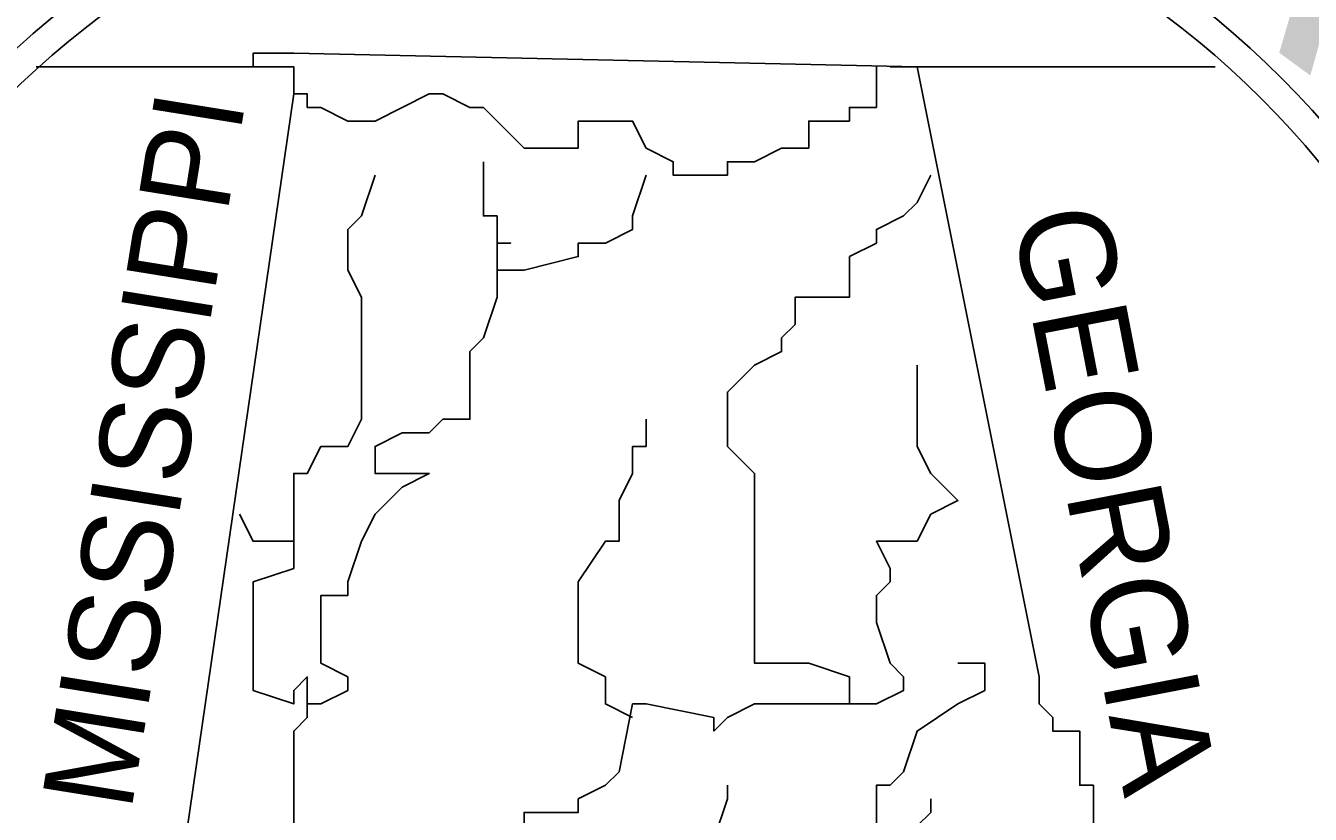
# Model space of a CAD drawing. Extents: x 0 to 1700, y 31 to 1131.
# Drawn here: x 915.89 to 940.79, y 79.02 to 94.3 of the extents above; entities that cross this region are included whole.
import ezdxf

# ---------------------------------------------------------------- set-up
doc = ezdxf.new("R2010")
doc.units = 0
doc.layers.add('great seal', color=7, linetype='Continuous')

msp = doc.modelspace()

# ---------------------------------------------------------------- linework, layer by layer
at = {"layer": 'great seal'}
for p, q in [((921.082, 93.503), (916.09, 93.503)), ((921.082, 93.503), (916.09, 93.503)), ((921.082, 93.503), (916.09, 93.503)), ((932.644, 93.503), (938.95, 93.503)), ((932.644, 93.503), (938.95, 93.503)), ((932.644, 93.503), (938.95, 93.503)), ((927.651, 80.891), (927.651, 80.891)), ((927.651, 80.891), (927.651, 80.891)), ((927.651, 80.891), (927.651, 80.891)), ((927.651, 80.891), (927.651, 80.891)), ((927.651, 80.891), (927.651, 80.891)), ((927.651, 80.891), (927.651, 80.891))]:
    msp.add_line(p, q, dxfattribs=at)
for points in [[(918.717, 76.687), (921.082, 92.978), (921.082, 93.503), (921.082, 93.503), (921.082, 93.503), (920.294, 93.503), (920.294, 93.766), (921.082, 93.766), (933.169, 93.503), (935.534, 81.679), (935.534, 81.154), (935.797, 80.891), (935.797, 80.628), (935.797, 80.628), (936.323, 80.628), (936.323, 79.84), (936.323, 79.577), (936.585, 79.577), (936.585, 79.314), (936.585, 79.314), (936.585, 79.051), (936.585, 78.789)], [(918.717, 76.687), (921.082, 92.978), (921.082, 93.503), (921.082, 93.503), (921.082, 93.503), (920.294, 93.503), (920.294, 93.766), (921.082, 93.766), (933.169, 93.503), (935.534, 81.679), (935.534, 81.154), (935.797, 80.891), (935.797, 80.628), (935.797, 80.628), (936.323, 80.628), (936.323, 79.84), (936.323, 79.577), (936.585, 79.577), (936.585, 79.314), (936.585, 79.314), (936.585, 79.051), (936.585, 78.789)], [(918.717, 76.687), (921.082, 92.978), (921.082, 93.503), (921.082, 93.503), (921.082, 93.503), (920.294, 93.503), (920.294, 93.766), (921.082, 93.766), (933.169, 93.503), (935.534, 81.679), (935.534, 81.154), (935.797, 80.891), (935.797, 80.628), (935.797, 80.628), (936.323, 80.628), (936.323, 79.84), (936.323, 79.577), (936.585, 79.577), (936.585, 79.314), (936.585, 79.314), (936.585, 79.051), (936.585, 78.789)], [(932.381, 93.503), (932.381, 93.503), (932.381, 93.503), (932.381, 92.978), (932.381, 92.715), (932.381, 92.715), (931.856, 92.715), (931.856, 92.715), (931.856, 92.452), (931.067, 92.452), (931.067, 91.927), (930.542, 91.927), (930.016, 91.664), (929.753, 91.664), (929.491, 91.664), (929.491, 91.401), (929.228, 91.401), (929.228, 91.401), (928.44, 91.401), (928.44, 91.401), (928.44, 91.664), (927.914, 91.927), (927.651, 92.452), (927.651, 92.452), (927.126, 92.452), (926.6, 92.452), (926.6, 91.927), (925.549, 91.927), (925.024, 92.452), (924.761, 92.715), (924.498, 92.715), (923.973, 92.978), (923.71, 92.978), (923.184, 92.715), (923.184, 92.715), (922.659, 92.452), (922.396, 92.452), (922.133, 92.452), (921.608, 92.715), (921.608, 92.715), (921.608, 92.715), (921.345, 92.715), (921.345, 92.715), (921.345, 92.715), (921.345, 92.978), (921.082, 92.978), (921.082, 93.503), (921.082, 93.503), (921.082, 93.503)], [(932.381, 93.503), (932.381, 93.503), (932.381, 93.503), (932.381, 92.978), (932.381, 92.715), (932.381, 92.715), (931.856, 92.715), (931.856, 92.715), (931.856, 92.452), (931.067, 92.452), (931.067, 91.927), (930.542, 91.927), (930.016, 91.664), (929.753, 91.664), (929.491, 91.664), (929.491, 91.401), (929.228, 91.401), (929.228, 91.401), (928.44, 91.401), (928.44, 91.401), (928.44, 91.664), (927.914, 91.927), (927.651, 92.452), (927.651, 92.452), (927.126, 92.452), (926.6, 92.452), (926.6, 91.927), (925.549, 91.927), (925.024, 92.452), (924.761, 92.715), (924.498, 92.715), (923.973, 92.978), (923.71, 92.978), (923.184, 92.715), (923.184, 92.715), (922.659, 92.452), (922.396, 92.452), (922.133, 92.452), (921.608, 92.715), (921.608, 92.715), (921.608, 92.715), (921.345, 92.715), (921.345, 92.715), (921.345, 92.715), (921.345, 92.978), (921.082, 92.978), (921.082, 93.503), (921.082, 93.503), (921.082, 93.503)], [(932.381, 93.503), (932.381, 93.503), (932.381, 93.503), (932.381, 92.978), (932.381, 92.715), (932.381, 92.715), (931.856, 92.715), (931.856, 92.715), (931.856, 92.452), (931.067, 92.452), (931.067, 91.927), (930.542, 91.927), (930.016, 91.664), (929.753, 91.664), (929.491, 91.664), (929.491, 91.401), (929.228, 91.401), (929.228, 91.401), (928.44, 91.401), (928.44, 91.401), (928.44, 91.664), (927.914, 91.927), (927.651, 92.452), (927.651, 92.452), (927.126, 92.452), (926.6, 92.452), (926.6, 91.927), (925.549, 91.927), (925.024, 92.452), (924.761, 92.715), (924.498, 92.715), (923.973, 92.978), (923.71, 92.978), (923.184, 92.715), (923.184, 92.715), (922.659, 92.452), (922.396, 92.452), (922.133, 92.452), (921.608, 92.715), (921.608, 92.715), (921.608, 92.715), (921.345, 92.715), (921.345, 92.715), (921.345, 92.715), (921.345, 92.978), (921.082, 92.978), (921.082, 93.503), (921.082, 93.503), (921.082, 93.503)], [(925.024, 89.562), (925.024, 89.825), (925.024, 90.088), (925.286, 90.088), (925.024, 90.088), (925.024, 90.35), (925.024, 90.613), (924.761, 90.613), (924.761, 90.876), (924.761, 91.401), (924.761, 91.664)], [(925.024, 89.562), (925.024, 89.825), (925.024, 90.088), (925.286, 90.088), (925.024, 90.088), (925.024, 90.35), (925.024, 90.613), (924.761, 90.613), (924.761, 90.876), (924.761, 91.401), (924.761, 91.664)], [(925.024, 89.562), (925.024, 89.825), (925.024, 90.088), (925.286, 90.088), (925.024, 90.088), (925.024, 90.35), (925.024, 90.613), (924.761, 90.613), (924.761, 90.876), (924.761, 91.401), (924.761, 91.664)], [(921.082, 84.307), (921.082, 84.832), (921.082, 85.095), (921.082, 85.621), (921.345, 85.621), (921.608, 86.146), (922.133, 86.146), (922.396, 86.672), (922.396, 87.723), (922.396, 88.248), (922.396, 88.511), (922.396, 89.036), (922.133, 89.562), (922.133, 90.088), (922.133, 90.35), (922.396, 90.613), (922.659, 91.401)], [(921.082, 84.307), (921.082, 84.832), (921.082, 85.095), (921.082, 85.621), (921.345, 85.621), (921.608, 86.146), (922.133, 86.146), (922.396, 86.672), (922.396, 87.723), (922.396, 88.248), (922.396, 88.511), (922.396, 89.036), (922.133, 89.562), (922.133, 90.088), (922.133, 90.35), (922.396, 90.613), (922.659, 91.401)], [(921.082, 84.307), (921.082, 84.832), (921.082, 85.095), (921.082, 85.621), (921.345, 85.621), (921.608, 86.146), (922.133, 86.146), (922.396, 86.672), (922.396, 87.723), (922.396, 88.248), (922.396, 88.511), (922.396, 89.036), (922.133, 89.562), (922.133, 90.088), (922.133, 90.35), (922.396, 90.613), (922.659, 91.401)], [(921.345, 81.154), (921.345, 81.154), (921.608, 81.154), (921.608, 81.154), (922.133, 81.416), (922.133, 81.679), (921.608, 81.942), (921.608, 81.942), (921.608, 82.73), (921.608, 83.256), (922.133, 83.256), (922.133, 83.518), (922.396, 84.307), (922.659, 84.832), (923.184, 85.358), (923.71, 85.621), (923.184, 85.621), (922.659, 85.621), (922.659, 86.146), (923.184, 86.409), (923.184, 86.409), (923.71, 86.409), (923.973, 86.672), (923.973, 86.672), (924.498, 86.672), (924.498, 87.197), (924.498, 87.723), (924.498, 87.723), (924.498, 87.985), (924.761, 88.248), (925.024, 89.036), (925.024, 89.036), (925.024, 89.562), (925.286, 89.562), (925.549, 89.562), (925.549, 89.562), (926.6, 89.825), (926.6, 90.088), (927.126, 90.088), (927.651, 90.35), (927.651, 90.613), (927.914, 91.401)], [(921.345, 81.154), (921.345, 81.154), (921.608, 81.154), (921.608, 81.154), (922.133, 81.416), (922.133, 81.679), (921.608, 81.942), (921.608, 81.942), (921.608, 82.73), (921.608, 83.256), (922.133, 83.256), (922.133, 83.518), (922.396, 84.307), (922.659, 84.832), (923.184, 85.358), (923.71, 85.621), (923.184, 85.621), (922.659, 85.621), (922.659, 86.146), (923.184, 86.409), (923.184, 86.409), (923.71, 86.409), (923.973, 86.672), (923.973, 86.672), (924.498, 86.672), (924.498, 87.197), (924.498, 87.723), (924.498, 87.723), (924.498, 87.985), (924.761, 88.248), (925.024, 89.036), (925.024, 89.036), (925.024, 89.562), (925.286, 89.562), (925.549, 89.562), (925.549, 89.562), (926.6, 89.825), (926.6, 90.088), (927.126, 90.088), (927.651, 90.35), (927.651, 90.613), (927.914, 91.401)], [(921.345, 81.154), (921.345, 81.154), (921.608, 81.154), (921.608, 81.154), (922.133, 81.416), (922.133, 81.679), (921.608, 81.942), (921.608, 81.942), (921.608, 82.73), (921.608, 83.256), (922.133, 83.256), (922.133, 83.518), (922.396, 84.307), (922.659, 84.832), (923.184, 85.358), (923.71, 85.621), (923.184, 85.621), (922.659, 85.621), (922.659, 86.146), (923.184, 86.409), (923.184, 86.409), (923.71, 86.409), (923.973, 86.672), (923.973, 86.672), (924.498, 86.672), (924.498, 87.197), (924.498, 87.723), (924.498, 87.723), (924.498, 87.985), (924.761, 88.248), (925.024, 89.036), (925.024, 89.036), (925.024, 89.562), (925.286, 89.562), (925.549, 89.562), (925.549, 89.562), (926.6, 89.825), (926.6, 90.088), (927.126, 90.088), (927.651, 90.35), (927.651, 90.613), (927.914, 91.401)], [(931.856, 81.154), (931.856, 81.679), (931.067, 81.942), (930.804, 81.942), (930.016, 81.942), (930.016, 83.256), (930.016, 83.256), (930.016, 83.518), (930.016, 84.307), (930.016, 84.832), (930.016, 85.621), (929.491, 86.146), (929.491, 87.197), (930.016, 87.723), (930.542, 87.985), (930.542, 88.248), (930.804, 88.511), (930.804, 89.036), (931.856, 89.036), (931.856, 89.562), (931.856, 89.825), (932.381, 90.088), (932.381, 90.35), (932.907, 90.613), (933.169, 90.876), (933.432, 91.401)], [(931.856, 81.154), (931.856, 81.679), (931.067, 81.942), (930.804, 81.942), (930.016, 81.942), (930.016, 83.256), (930.016, 83.256), (930.016, 83.518), (930.016, 84.307), (930.016, 84.832), (930.016, 85.621), (929.491, 86.146), (929.491, 87.197), (930.016, 87.723), (930.542, 87.985), (930.542, 88.248), (930.804, 88.511), (930.804, 89.036), (931.856, 89.036), (931.856, 89.562), (931.856, 89.825), (932.381, 90.088), (932.381, 90.35), (932.907, 90.613), (933.169, 90.876), (933.432, 91.401)], [(931.856, 81.154), (931.856, 81.679), (931.067, 81.942), (930.804, 81.942), (930.016, 81.942), (930.016, 83.256), (930.016, 83.256), (930.016, 83.518), (930.016, 84.307), (930.016, 84.832), (930.016, 85.621), (929.491, 86.146), (929.491, 87.197), (930.016, 87.723), (930.542, 87.985), (930.542, 88.248), (930.804, 88.511), (930.804, 89.036), (931.856, 89.036), (931.856, 89.562), (931.856, 89.825), (932.381, 90.088), (932.381, 90.35), (932.907, 90.613), (933.169, 90.876), (933.432, 91.401)], [(925.549, 78.526), (925.549, 79.051), (926.6, 79.051), (926.6, 79.314), (926.6, 79.314), (927.126, 79.577), (927.389, 79.84), (927.651, 81.154), (927.914, 81.154), (929.228, 80.891), (929.228, 80.628), (929.491, 80.891), (930.016, 81.154), (930.804, 81.154), (931.856, 81.154), (932.381, 81.154), (932.907, 81.416), (932.907, 81.679), (932.644, 81.942), (932.644, 81.942), (932.381, 82.73), (932.381, 83.256), (932.644, 83.518), (932.644, 83.781), (932.381, 84.307), (933.169, 84.307), (933.432, 84.832), (933.958, 85.095), (933.432, 85.621), (933.432, 85.621), (933.169, 86.146), (933.169, 86.672), (933.169, 87.723)], [(925.549, 78.526), (925.549, 79.051), (926.6, 79.051), (926.6, 79.314), (926.6, 79.314), (927.126, 79.577), (927.389, 79.84), (927.651, 81.154), (927.914, 81.154), (929.228, 80.891), (929.228, 80.628), (929.491, 80.891), (930.016, 81.154), (930.804, 81.154), (931.856, 81.154), (932.381, 81.154), (932.907, 81.416), (932.907, 81.679), (932.644, 81.942), (932.644, 81.942), (932.381, 82.73), (932.381, 83.256), (932.644, 83.518), (932.644, 83.781), (932.381, 84.307), (933.169, 84.307), (933.432, 84.832), (933.958, 85.095), (933.432, 85.621), (933.432, 85.621), (933.169, 86.146), (933.169, 86.672), (933.169, 87.723)], [(925.549, 78.526), (925.549, 79.051), (926.6, 79.051), (926.6, 79.314), (926.6, 79.314), (927.126, 79.577), (927.389, 79.84), (927.651, 81.154), (927.914, 81.154), (929.228, 80.891), (929.228, 80.628), (929.491, 80.891), (930.016, 81.154), (930.804, 81.154), (931.856, 81.154), (932.381, 81.154), (932.907, 81.416), (932.907, 81.679), (932.644, 81.942), (932.644, 81.942), (932.381, 82.73), (932.381, 83.256), (932.644, 83.518), (932.644, 83.781), (932.381, 84.307), (933.169, 84.307), (933.432, 84.832), (933.958, 85.095), (933.432, 85.621), (933.432, 85.621), (933.169, 86.146), (933.169, 86.672), (933.169, 87.723)], [(927.651, 80.891), (927.126, 81.154), (927.126, 81.416), (927.126, 81.679), (926.6, 81.942), (926.6, 82.73), (926.6, 83.256), (926.6, 83.518), (926.6, 83.518), (927.126, 84.307), (927.389, 84.307), (927.389, 85.095), (927.651, 85.621), (927.651, 85.621), (927.651, 86.146), (927.914, 86.146), (927.914, 86.672)], [(927.651, 80.891), (927.126, 81.154), (927.126, 81.416), (927.126, 81.679), (926.6, 81.942), (926.6, 82.73), (926.6, 83.256), (926.6, 83.518), (926.6, 83.518), (927.126, 84.307), (927.389, 84.307), (927.389, 85.095), (927.651, 85.621), (927.651, 85.621), (927.651, 86.146), (927.914, 86.146), (927.914, 86.672)], [(927.651, 80.891), (927.126, 81.154), (927.126, 81.416), (927.126, 81.679), (926.6, 81.942), (926.6, 82.73), (926.6, 83.256), (926.6, 83.518), (926.6, 83.518), (927.126, 84.307), (927.389, 84.307), (927.389, 85.095), (927.651, 85.621), (927.651, 85.621), (927.651, 86.146), (927.914, 86.146), (927.914, 86.672)], [(921.082, 78.789), (921.082, 79.314), (921.082, 79.314), (921.082, 79.577), (921.082, 80.628), (921.082, 80.628), (921.345, 80.891), (921.345, 81.154), (921.345, 81.679), (921.082, 81.416), (921.082, 81.154), (920.294, 81.416), (920.294, 81.679), (920.294, 81.942), (920.294, 81.942), (920.294, 83.256), (920.294, 83.256), (920.294, 83.518), (921.082, 83.781), (921.082, 84.307), (920.294, 84.307), (920.031, 84.832), (920.031, 84.832)], [(921.082, 78.789), (921.082, 79.314), (921.082, 79.314), (921.082, 79.577), (921.082, 80.628), (921.082, 80.628), (921.345, 80.891), (921.345, 81.154), (921.345, 81.679), (921.082, 81.416), (921.082, 81.154), (920.294, 81.416), (920.294, 81.679), (920.294, 81.942), (920.294, 81.942), (920.294, 83.256), (920.294, 83.256), (920.294, 83.518), (921.082, 83.781), (921.082, 84.307), (920.294, 84.307), (920.031, 84.832), (920.031, 84.832)], [(921.082, 78.789), (921.082, 79.314), (921.082, 79.314), (921.082, 79.577), (921.082, 80.628), (921.082, 80.628), (921.345, 80.891), (921.345, 81.154), (921.345, 81.679), (921.082, 81.416), (921.082, 81.154), (920.294, 81.416), (920.294, 81.679), (920.294, 81.942), (920.294, 81.942), (920.294, 83.256), (920.294, 83.256), (920.294, 83.518), (921.082, 83.781), (921.082, 84.307), (920.294, 84.307), (920.031, 84.832), (920.031, 84.832)], [(929.228, 74.059), (929.228, 74.059), (929.228, 74.847), (929.491, 75.11), (929.491, 75.373), (929.491, 75.898), (929.753, 75.898), (930.016, 76.424), (930.804, 76.687), (931.067, 77.212), (931.856, 77.212), (931.856, 77.738), (932.381, 78.789), (932.381, 79.314), (932.381, 79.314), (932.381, 79.577), (932.644, 79.577), (932.907, 79.84), (933.169, 80.628), (933.958, 81.154), (934.483, 81.416), (934.483, 81.679), (934.483, 81.942), (933.958, 81.942)], [(929.228, 74.059), (929.228, 74.059), (929.228, 74.847), (929.491, 75.11), (929.491, 75.373), (929.491, 75.898), (929.753, 75.898), (930.016, 76.424), (930.804, 76.687), (931.067, 77.212), (931.856, 77.212), (931.856, 77.738), (932.381, 78.789), (932.381, 79.314), (932.381, 79.314), (932.381, 79.577), (932.644, 79.577), (932.907, 79.84), (933.169, 80.628), (933.958, 81.154), (934.483, 81.416), (934.483, 81.679), (934.483, 81.942), (933.958, 81.942)], [(929.228, 74.059), (929.228, 74.059), (929.228, 74.847), (929.491, 75.11), (929.491, 75.373), (929.491, 75.898), (929.753, 75.898), (930.016, 76.424), (930.804, 76.687), (931.067, 77.212), (931.856, 77.212), (931.856, 77.738), (932.381, 78.789), (932.381, 79.314), (932.381, 79.314), (932.381, 79.577), (932.644, 79.577), (932.907, 79.84), (933.169, 80.628), (933.958, 81.154), (934.483, 81.416), (934.483, 81.679), (934.483, 81.942), (933.958, 81.942)], [(929.228, 78.526), (929.491, 79.314), (929.491, 79.314), (929.491, 79.577)], [(929.228, 78.526), (929.491, 79.314), (929.491, 79.314), (929.491, 79.577)], [(929.228, 78.526), (929.491, 79.314), (929.491, 79.314), (929.491, 79.577)], [(933.169, 78.789), (933.432, 79.051), (933.432, 79.314)], [(933.169, 78.789), (933.432, 79.051), (933.432, 79.314)], [(933.169, 78.789), (933.432, 79.051), (933.432, 79.314)]]:
    msp.add_lwpolyline(points, dxfattribs=at)
for radius in [22.994, 22.994, 22.994, 22.389, 22.389, 22.389, 17.779, 17.779, 17.779, 17.222, 17.222, 17.222]:
    msp.add_circle((927.669, 80.706), radius, dxfattribs=at)

# ---------------------------------------------------------------- texts
for s, height, rotation, p in [('A', 5.848, 323.9887, (936.585, 96.394)), ('A', 5.848, 323.9887, (936.585, 96.394)), ('A', 5.848, 323.9887, (936.585, 96.394)), ('MISSISSIPPI', 1.75474, 80.8531, (917.929, 79.051)), ('MISSISSIPPI', 1.75474, 80.8531, (917.929, 79.051)), ('MISSISSIPPI', 1.75474, 80.8531, (917.929, 79.051)), ('GEORGIA', 1.8446, 280.9296, (935.009, 90.613)), ('GEORGIA', 1.8446, 280.9296, (935.009, 90.613)), ('GEORGIA', 1.8446, 280.9296, (935.009, 90.613))]:
    msp.add_text(s, height=height, rotation=rotation, dxfattribs=at).set_placement(p)

doc.saveas('drawing.dxf')
